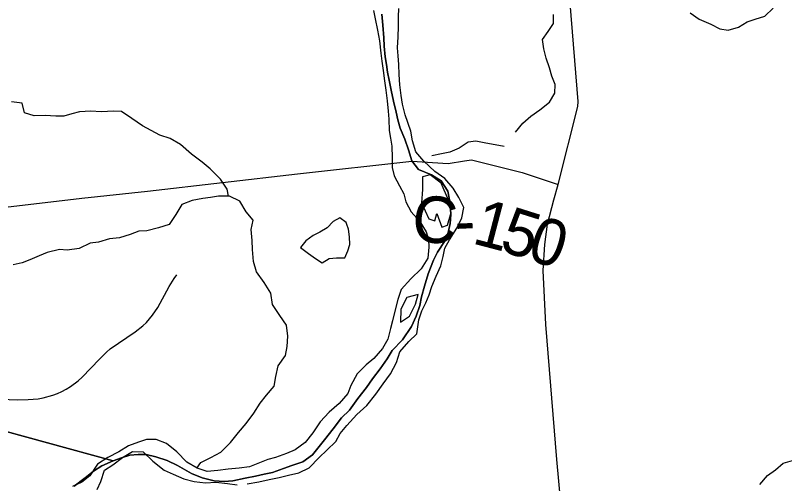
# Model space of a CAD drawing. Extents: x 114604 to 551442, y 316898 to 567001.
# Drawn here: x 132822 to 137786, y 402219 to 405241 of the extents above; entities that cross this region are included whole.
import ezdxf

# ---------------------------------------------------------------- set-up
doc = ezdxf.new("R2010")
doc.units = 0
for name, color, linetype in [('DV_X_County_Line', 7, 'Continuous'), ('GE_P_Alignment_1000_Cardinal_Points', 7, 'Continuous'), ('GE_P_Alignment_500_Bearings', 7, 'Continuous'), ('GE_P_Alignment_500_Distances', 7, 'Continuous'), ('MT_X_Edge_Line', 7, 'Continuous'), ('PM_P_Cells', 7, 'Continuous'), ('PM_P_CL_Double_Solid', 7, 'Continuous'), ('RS_Raster1', 7, 'Continuous')]:
    doc.layers.add(name, color=color, linetype=linetype)

msp = doc.modelspace()

# ---------------------------------------------------------------- linework, layer by layer
at = {"layer": 'DV_X_County_Line'}
for points in [[(135132.6, 405272.6), (135142.5, 405218.5), (135158.5, 405146.3), (135170.5, 405076.1), (135180.5, 404997.9), (135186.5, 404945.7), (135194.4, 404885.6), (135204.4, 404817.4), (135212.4, 404757.2), (135220.3, 404689), (135228.3, 404622.9), (135232.3, 404570.7), (135234.2, 404498.5), (135242.2, 404448.4), (135250.2, 404396.3), (135252.1, 404322.1), (135254.1, 404257.9), (135266.1, 404205.8), (135300.1, 404139.6), (135328.1, 404089.4), (135342.1, 404037.3), (135376.2, 403973.1), (135432.3, 403910.9), (135472.3, 403844.7), (135488.3, 403794.6), (135490.3, 403744.4), (135482.2, 403674.3), (135440, 403604.1), (135373.8, 403540), (135311.6, 403471.8), (135289.5, 403407.7), (135271.4, 403339.5), (135255.4, 403269.3), (135243.3, 403219.2), (135225.2, 403151), (135191.1, 403090.9), (135134.9, 403026.8), (135084.7, 402984.7), (135026.5, 402926.6), (134986.4, 402852.4), (134966.3, 402800.3), (134910.1, 402736.1), (134845.9, 402680), (134787.7, 402617.9), (134741.6, 402545.8), (134691.4, 402483.6), (134627.2, 402437.5), (134571.1, 402413.5), (134500.9, 402387.5), (134450.8, 402373.5), (134386.6, 402347.4), (134332.4, 402327.4), (134266.3, 402317.5), (134194.1, 402311.5), (134127.9, 402303.5), (134059.8, 402297.5), (133995.6, 402317.6), (133927.5, 402357.8), (133863.4, 402424), (133797.3, 402478.2), (133729.1, 402504.3), (133667, 402502.3), (133616.9, 402486.3), (133550.7, 402462.3), (133488.5, 402424.2), (133418.3, 402388.1), (133352.1, 402344.1), (133301.9, 402267.9), (133249.8, 402227.8), (133189.6, 402199.8)], [(134318.3, 402217.1), (134392.5, 402229.1), (134458.7, 402245.1), (134522.8, 402259.1), (134583, 402273.1), (134651.2, 402287.1), (134717.3, 402321.2), (134781.6, 402387.3), (134831.7, 402433.4), (134889.9, 402489.5), (134918, 402541.6), (134960.1, 402593.8), (135024.3, 402663.9), (135088.5, 402722), (135148.7, 402796.2), (135194.9, 402862.3), (135243.1, 402926.5), (135281.2, 403000.6), (135303.3, 403068.8), (135361.5, 403134.9), (135411.7, 403185), (135425.8, 403275.2), (135443.9, 403333.4), (135469.9, 403385.5), (135492, 403437.6), (135508.1, 403489.8), (135536.2, 403557.9), (135566.4, 403624.1), (135582.4, 403684.2), (135592.5, 403738.4), (135622.6, 403792.5), (135670.8, 403866.6), (135702.9, 403934.8), (135715, 404001), (135683, 404065.1), (135646.9, 404125.3), (135592.8, 404187.5), (135528.7, 404233.7), (135456.6, 404299.9), (135406.5, 404360.1), (135384.5, 404430.3), (135372.6, 404494.4), (135336.5, 404598.8), (135320.6, 404666.9), (135310.6, 404723.1), (135302.6, 404793.3), (135298.7, 404859.5), (135296.7, 404923.6), (135290.7, 404979.8), (135286.8, 405031.9), (135290.8, 405102.1), (135292.9, 405168.3), (135294.9, 405232.4), (135297, 405284.6)], [(135448.5, 404199.6), (135448.5, 404117.4), (135442.4, 404031.2), (135490.4, 403926.9), (135528.5, 403914.9), (135540.6, 403961), (135572.6, 403872.7), (135610.7, 403886.7), (135632.8, 403968.9)], [(135632.8, 403968.9), (135616.8, 404049.1), (135568.8, 404157.5), (135498.6, 404211.6), (135448.5, 404199.6)], [(135307.5, 403261.3), (135365.6, 403299.3), (135403.8, 403377.5), (135419.9, 403439.7)], [(135419.9, 403439.7), (135347.7, 403419.7), (135309.5, 403345.5), (135307.5, 403261.3)], [(133350, 402179.6), (133372.1, 402231.8), (133396.2, 402305.9), (133450.3, 402340), (133512.5, 402386.1), (133576.7, 402426.1), (133646.9, 402424.1), (133709, 402363.9), (133781.1, 402305.7), (133839.2, 402279.6), (133909.4, 402249.5), (133975.5, 402231.4), (134047.7, 402223.3), (134115.8, 402227.3), (134190, 402219.2), (134252.2, 402211.2)]]:
    msp.add_lwpolyline(points, dxfattribs=at)
at = {"layer": 'GE_P_Alignment_1000_Cardinal_Points'}
msp.add_lwpolyline([(132612, 402768.8), (132838.5, 402760.3), (132903.9, 402760.9), (132968.3, 402766.2), (133000.2, 402771.4), (133063.3, 402788.6), (133093.1, 402800), (133122.1, 402813.2), (133150.4, 402828.5), (133177.5, 402845.6), (133227.2, 402883), (133252.3, 402906.2), (133363.7, 403022.1), (133409.7, 403067.1), (133433.7, 403088.4), (133594.1, 403197.4), (133643.9, 403236.2), (133667.1, 403259.4), (133706.4, 403305.9), (133741.3, 403355.8), (133814.3, 403489.8), (133846.1, 403541.9), (133864.1, 403567.1)], dxfattribs=at)
at = {"layer": 'GE_P_Alignment_500_Bearings'}
for points in [[(137819, 397611.5), (137569.2, 397769.1), (137460.2, 397857.6), (137361.7, 397967.5), (137265.2, 398087.9), (137083.9, 398327.9), (136928.8, 398615.9), (136859.3, 398819.5), (136731.5, 399219.5), (136594.3, 399866), (136518.1, 400325), (136466.8, 400710.6), (136445.7, 401007.4), (136395.8, 401510.7), (136316.6, 402375), (136245.4, 403245.3), (136228.1, 403594.2), (136237.5, 403762.8), (136255.1, 403893.3), (136296.6, 404049.9), (136324.2, 404148.4), (136450.6, 404652.5), (136452.5, 404684.6), (136402.2, 405320.3)], [(132646.2, 403990.7), (133250.5, 404060.6), (133674.4, 404106.8), (134642.3, 404218), (135380.9, 404298.8)], [(135380.9, 404298.8), (135614.8, 404285.6), (135718.9, 404302.1), (135764.9, 404308.3), (135833.1, 404290.6), (136091.7, 404225.6), (136324.2, 404148.4)]]:
    msp.add_lwpolyline(points, dxfattribs=at)
at = {"layer": 'GE_P_Alignment_500_Distances'}
for points in [[(135186.8, 405248.9), (135192.5, 405176.6), (135198.2, 405096.3), (135202, 405042.1), (135207.8, 404973.8), (135215.6, 404923.6), (135223.4, 404873.4), (135233.2, 404823.2), (135247.1, 404758.9), (135260.8, 404686.6), (135278.6, 404616.3), (135290.4, 404566.1), (135304.3, 404513.8), (135334.1, 404441.5), (135357.9, 404373.1), (135379.7, 404301.6), (135423.7, 404246.5), (135505.9, 404212.1), (135570, 404173.7), (135611.9, 404105.3), (135627.6, 404027), (135631.3, 403954.7), (135627.1, 403898.5), (135614.8, 403840.3), (135594.5, 403788.2), (135546, 403712.1), (135519.7, 403660), (135485.2, 403571.8), (135460.7, 403493.6), (135442.4, 403423.4), (135432.1, 403367.2), (135407.7, 403299), (135377.3, 403232.9), (135320.7, 403146.8), (135254.1, 403076.8), (135221.8, 403024.6), (135175.3, 402958.6), (135126.8, 402894.5), (135088.4, 402838.4), (135031.9, 402768.3), (134977.4, 402692.3), (134926.9, 402642.3), (134872.4, 402572.2), (134815.9, 402500.1), (134739.2, 402404), (134676.7, 402360.1), (134606.3, 402336.2), (134552, 402316.3), (134481.6, 402290.4), (134427.3, 402278.6), (134371, 402266.7), (134304.7, 402252.9), (134224.3, 402237.1), (134168.1, 402231.3), (134103.8, 402235.5), (134027.5, 402255.8), (133957.4, 402284.2), (133867.2, 402334.7), (133801.1, 402367), (133728.8, 402391.3), (133664.6, 402405.6), (133614.4, 402405.8), (133560.2, 402401.9), (133505.9, 402384.1), (133453.3, 402365.7), (132602.9, 402598.1)], [(133201.9, 402202.4), (133272.4, 402256.4), (133324.8, 402298.3), (133379.1, 402334.3), (133453.3, 402365.7), (133505.9, 402384.1), (133560.2, 402401.9), (133614.4, 402405.8), (133664.6, 402405.6), (133728.8, 402391.3), (133801.1, 402367), (133867.2, 402334.7), (133957.4, 402284.2), (134027.5, 402255.8), (134103.8, 402235.5), (134168.1, 402231.3), (134224.3, 402237.1), (134304.7, 402252.9), (134371, 402266.7), (134427.3, 402278.6), (134481.6, 402290.4), (134552, 402316.3), (134606.3, 402336.2), (134676.7, 402360.1), (134739.2, 402404), (134815.9, 402500.1), (134872.4, 402572.2), (134926.9, 402642.3), (134977.4, 402692.3), (135031.9, 402768.3), (135088.4, 402838.4), (135126.8, 402894.5), (135175.3, 402958.6), (135221.8, 403024.6), (135254.1, 403076.8), (135320.7, 403146.8), (135377.3, 403232.9), (135407.7, 403299), (135432.1, 403367.2), (135442.4, 403423.4), (135460.7, 403493.6), (135485.2, 403571.8), (135519.7, 403660), (135546, 403712.1), (135594.5, 403788.2), (135614.8, 403840.3), (135627.1, 403898.5), (135631.3, 403954.7), (135627.6, 404027), (135611.9, 404105.3), (135570, 404173.7), (135505.9, 404212.1), (135423.7, 404246.5), (135379.7, 404301.6), (135357.9, 404373.1), (135334.1, 404441.5), (135304.3, 404513.8), (135290.4, 404566.1), (135278.6, 404616.3), (135260.8, 404686.6), (135247.1, 404758.9), (135233.2, 404823.2), (135223.4, 404873.4), (135215.6, 404923.6), (135207.8, 404973.8), (135202, 405042.1), (135198.2, 405096.3), (135192.5, 405176.6), (135186.8, 405248.9)], [(132602.9, 402598.1), (133453.3, 402365.7), (133379.1, 402334.3), (133324.8, 402298.3), (133272.4, 402256.4), (133201.9, 402202.4)]]:
    msp.add_lwpolyline(points, dxfattribs=at)
at = {"layer": 'MT_X_Edge_Line'}
for points in [[(134960.8, 403890.8), (134955.8, 403904.7), (134915.8, 403934.9), (134871.7, 403911), (134833.4, 403869), (134785.2, 403841.1), (134743.1, 403819.2), (134696.9, 403785.3), (134660.6, 403743.3)], [(134660.6, 403743.3), (134712.6, 403703), (134758.5, 403670.8), (134802.4, 403642.6), (134846.6, 403670.5), (134894.7, 403676.3), (134946.8, 403676.2), (134967, 403720.2), (134979.2, 403762.2), (134977.4, 403812.4), (134971.6, 403860.5), (134960.8, 403890.8)]]:
    msp.add_lwpolyline(points, dxfattribs=at)
at = {"layer": 'PM_P_Cells'}
for points in [[(137176.9, 405257.9), (137234.7, 405215.4), (137308.5, 405184.9), (137368.3, 405154.5), (137422.3, 405146.1), (137488.4, 405163.8), (137544.6, 405199.5), (137594.7, 405215.3), (137658.9, 405234.9), (137711.1, 405286.8)], [(136048.3, 404486.7), (136096.7, 404544.5), (136148.9, 404590.3), (136205.2, 404632.1), (136267.5, 404679.8), (136303.8, 404737.8), (136304.1, 404793.9), (136284.4, 404848.2), (136268.8, 404902.4), (136247.1, 404964.7), (136231.4, 405024.9), (136223.8, 405085.1), (136260.1, 405137), (136294.4, 405189), (136294.7, 405247.1)], [(134197.3, 404073.8), (134187.4, 404119.9), (134145.6, 404184.2), (134077.8, 404250.6), (134025.9, 404292.9), (133958, 404345.3), (133888.2, 404407.7), (133820.2, 404446), (133754.2, 404468.3), (133698.2, 404498.6), (133642.3, 404526.8), (133572.3, 404575.2), (133506.4, 404619.5), (133456.4, 404621.7), (133376.2, 404618), (133308.1, 404622.2), (133236, 404618.5), (133185.9, 404604.6), (133133.7, 404590.8), (133083.6, 404591), (133013.5, 404595.2), (132943.4, 404591.5), (132879.4, 404611.7), (132865.6, 404673.9), (132797.6, 404682.2)], [(135975.1, 404393.6), (135847, 404418.8), (135793, 404429.3), (135742.8, 404421.7), (135686.3, 404384.1), (135625.9, 404358.6), (135571.6, 404347), (135509.3, 404333.5)], [(133993.5, 402318.8), (134017.9, 402354.3), (134082.1, 402386.1), (134146.4, 402422), (134210.7, 402483.9), (134261.1, 402547.9), (134311.4, 402605.8), (134359.7, 402673.8), (134402.1, 402737.8), (134442.3, 402789.8), (134490.7, 402847.8), (134502.9, 402909.9), (134517.2, 402978), (134565.6, 403046), (134575.9, 403104.1), (134580.1, 403170.2), (134570.4, 403240.4), (134528.6, 403304.7), (134480.8, 403375.1), (134471.1, 403447.3), (134427.3, 403515.6), (134377.5, 403586), (134357.8, 403652.2), (134352.1, 403730.4), (134350.3, 403788.5), (134342.6, 403858.7), (134356.9, 403918.8), (134311, 403973.1), (134269.2, 404041.4), (134203.3, 404073.7), (134133.2, 404074), (134081, 404064.2), (134030.9, 404058.3), (133962.8, 404046.5), (133896.6, 404020.7), (133856.2, 403954.7), (133813.9, 403890.7), (133745.7, 403868.9), (133669.5, 403851.1), (133617.4, 403847.3), (133563.2, 403827.4), (133493, 403805.6), (133428.9, 403797.8), (133358.7, 403776), (133304.6, 403770.2), (133234.3, 403736.4), (133156.2, 403724.6), (133106.1, 403728.8), (133025.9, 403711), (132975.7, 403689.2), (132915.5, 403663.3), (132865.4, 403643.4), (132807.2, 403629.6)], [(137625.6, 402213.5), (137675.9, 402271.4), (137726.1, 402307.1), (137776.4, 402351), (137836.5, 402368.7)]]:
    msp.add_lwpolyline(points, dxfattribs=at)
at = {"layer": 'RS_Raster1'}
for points in [[(135186.8, 405248.9), (135192.5, 405176.6), (135198.2, 405096.3), (135202, 405042.1), (135207.8, 404973.8), (135215.6, 404923.6), (135223.4, 404873.4), (135233.2, 404823.2), (135247.1, 404758.9), (135260.8, 404686.6), (135278.6, 404616.3), (135290.4, 404566.1), (135304.3, 404513.8), (135334.1, 404441.5), (135357.9, 404373.1), (135379.7, 404301.6), (135423.7, 404246.5), (135505.9, 404212.1), (135570, 404173.7), (135611.9, 404105.3), (135627.6, 404027), (135631.3, 403954.7), (135627.1, 403898.5), (135614.8, 403840.3), (135594.5, 403788.2), (135546, 403712.1), (135519.7, 403660), (135485.2, 403571.8), (135460.7, 403493.6), (135442.4, 403423.4), (135432.1, 403367.2), (135407.7, 403299), (135377.3, 403232.9), (135320.7, 403146.8), (135254.1, 403076.8), (135221.8, 403024.6), (135175.3, 402958.6), (135126.8, 402894.5), (135088.4, 402838.4), (135031.9, 402768.3), (134977.4, 402692.3), (134926.9, 402642.3), (134872.4, 402572.2), (134815.9, 402500.1), (134739.2, 402404), (134676.7, 402360.1), (134606.3, 402336.2), (134552, 402316.3), (134481.6, 402290.4), (134427.3, 402278.6), (134371, 402266.7), (134304.7, 402252.9), (134224.3, 402237.1), (134168.1, 402231.3), (134103.8, 402235.5), (134027.5, 402255.8), (133957.4, 402284.2), (133867.2, 402334.7), (133801.1, 402367), (133728.8, 402391.3), (133664.6, 402405.6), (133614.4, 402405.8), (133560.2, 402401.9), (133505.9, 402384.1), (133453.3, 402365.7), (133379.1, 402334.3), (133324.8, 402298.3), (133272.4, 402256.4), (133201.9, 402202.4)], [(133201.9, 402202.4), (133272.4, 402256.4), (133324.8, 402298.3), (133379.1, 402334.3), (133453.3, 402365.7), (133505.9, 402384.1), (133560.2, 402401.9), (133614.4, 402405.8), (133664.6, 402405.6), (133728.8, 402391.3), (133801.1, 402367), (133867.2, 402334.7), (133957.4, 402284.2), (134027.5, 402255.8), (134103.8, 402235.5), (134168.1, 402231.3), (134224.3, 402237.1), (134304.7, 402252.9), (134371, 402266.7), (134427.3, 402278.6), (134481.6, 402290.4), (134552, 402316.3), (134606.3, 402336.2), (134676.7, 402360.1), (134739.2, 402404), (134815.9, 402500.1), (134872.4, 402572.2), (134926.9, 402642.3), (134977.4, 402692.3), (135031.9, 402768.3), (135088.4, 402838.4), (135126.8, 402894.5), (135175.3, 402958.6), (135221.8, 403024.6), (135254.1, 403076.8), (135320.7, 403146.8), (135377.3, 403232.9), (135407.7, 403299), (135432.1, 403367.2), (135442.4, 403423.4), (135460.7, 403493.6), (135485.2, 403571.8), (135519.7, 403660), (135546, 403712.1), (135594.5, 403788.2), (135614.8, 403840.3), (135627.1, 403898.5), (135631.3, 403954.7), (135627.6, 404027), (135611.9, 404105.3), (135570, 404173.7), (135505.9, 404212.1), (135423.7, 404246.5), (135379.7, 404301.6), (135357.9, 404373.1), (135334.1, 404441.5), (135304.3, 404513.8), (135290.4, 404566.1), (135278.6, 404616.3), (135260.8, 404686.6), (135247.1, 404758.9), (135233.2, 404823.2), (135223.4, 404873.4), (135215.6, 404923.6), (135207.8, 404973.8), (135202, 405042.1), (135198.2, 405096.3), (135192.5, 405176.6), (135186.8, 405248.9)]]:
    msp.add_lwpolyline(points, dxfattribs=at)

# ---------------------------------------------------------------- texts
at = {"layer": 'PM_P_CL_Double_Solid'}
for s, rotation, p in [('C', 354.9194, (135372.1, 403785.9)), ('1', 345.3397, (135760.9, 403771.2)), ('5', 342.5279, (135935.9, 403725.5)), ('0', 341.8211, (136111.3, 403670.3)), ('-', 2.6051, (135661.5, 403763.1))]:
    msp.add_text(s, height=300, rotation=rotation, dxfattribs=at).set_placement(p)

doc.saveas('drawing.dxf')
